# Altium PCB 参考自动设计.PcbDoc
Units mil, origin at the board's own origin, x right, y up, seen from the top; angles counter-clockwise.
Board outline 2362.2 x 2362.2 mil, 2 copper layers (Top Layer, Bottom Layer); 30 components, 18 nets, 92 pads, 180 vias.
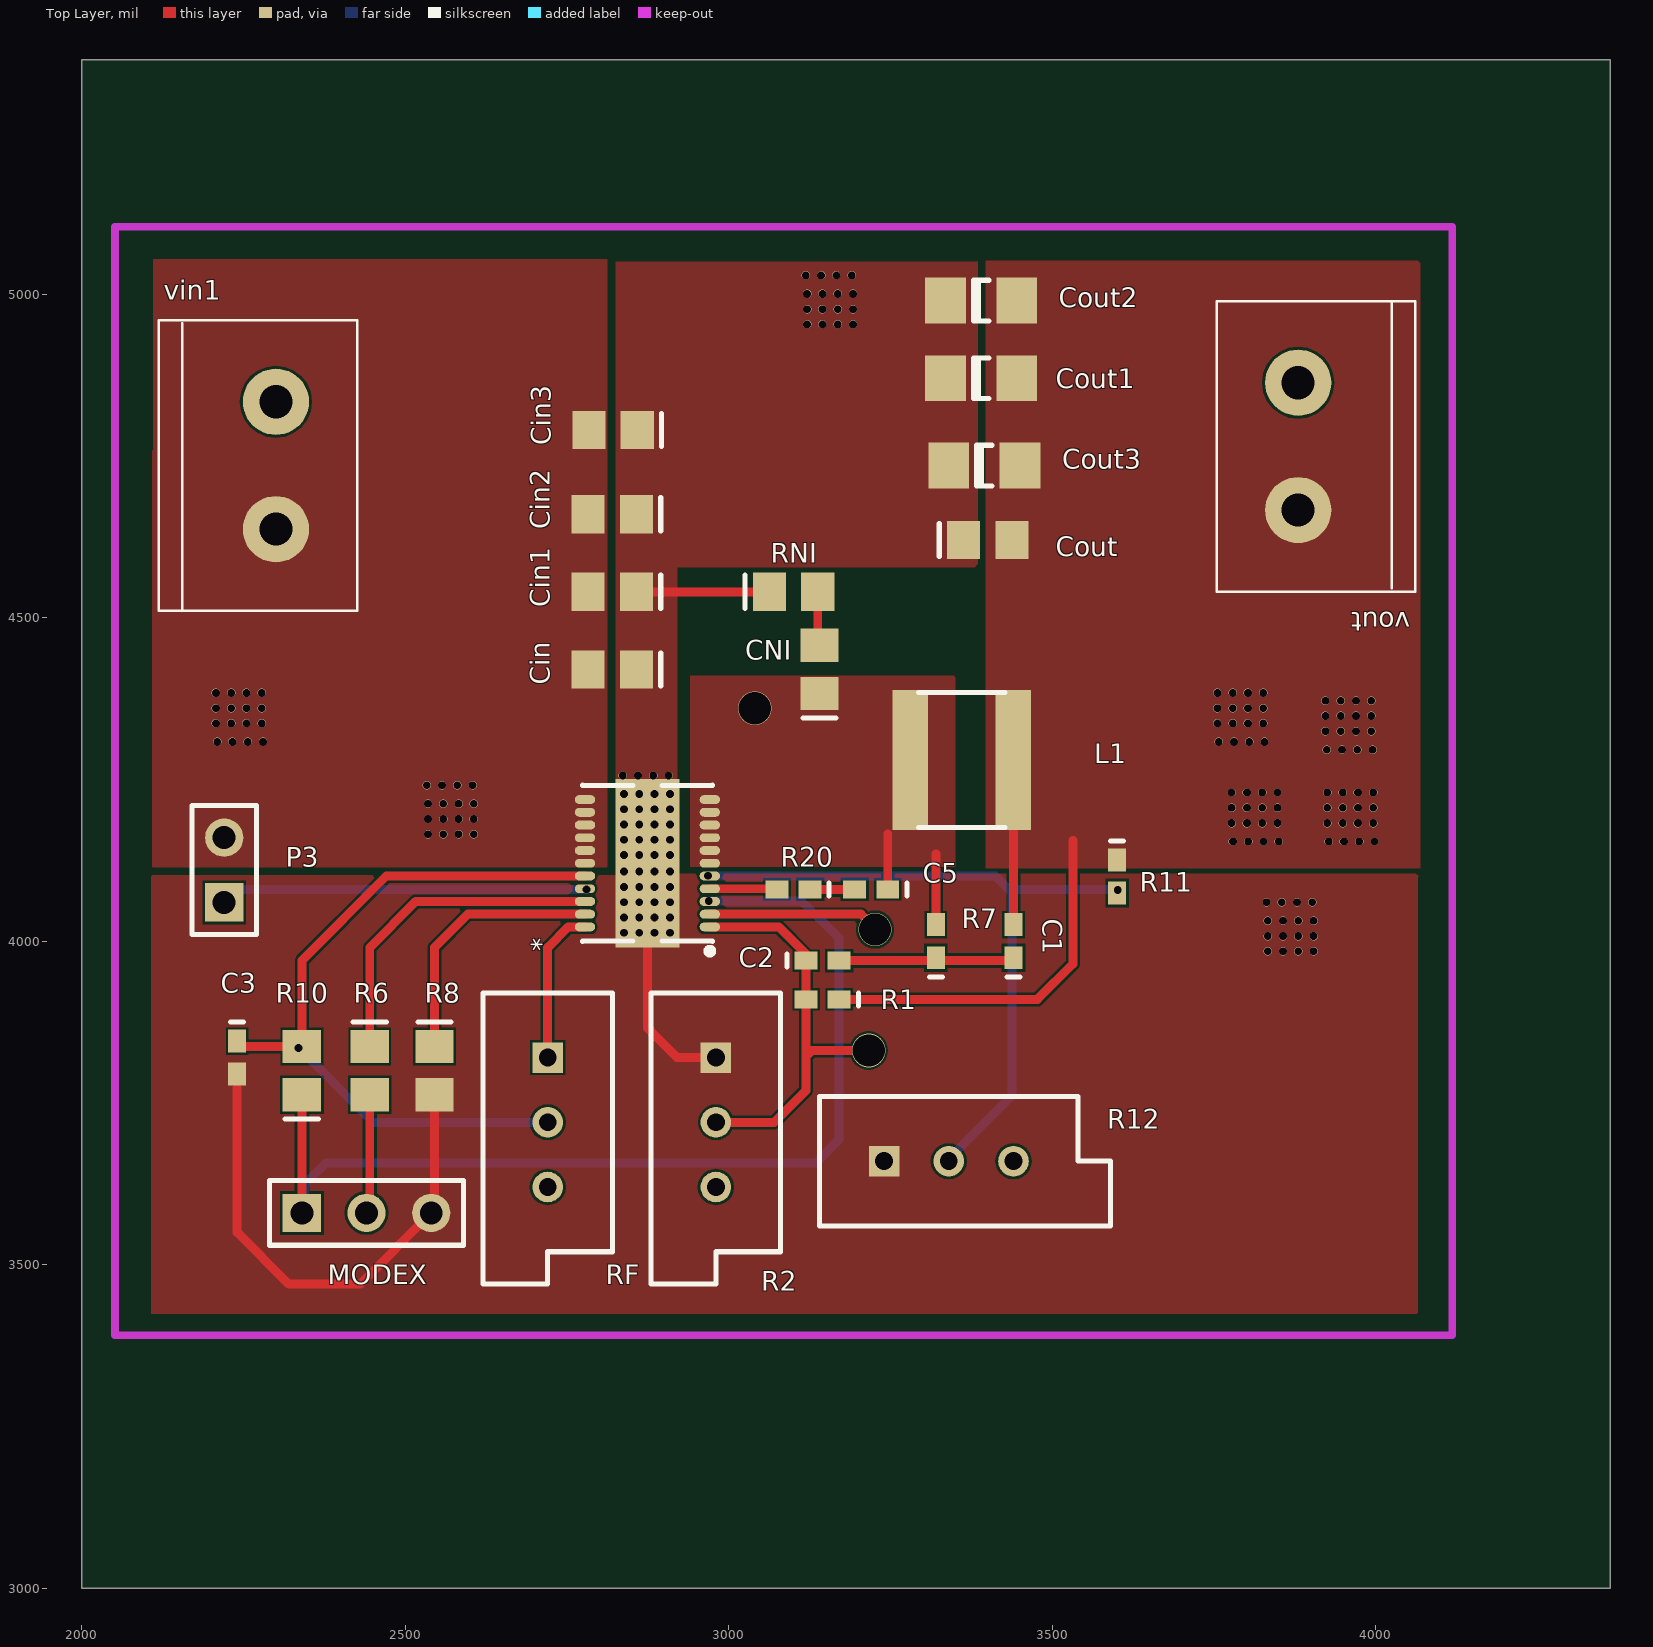
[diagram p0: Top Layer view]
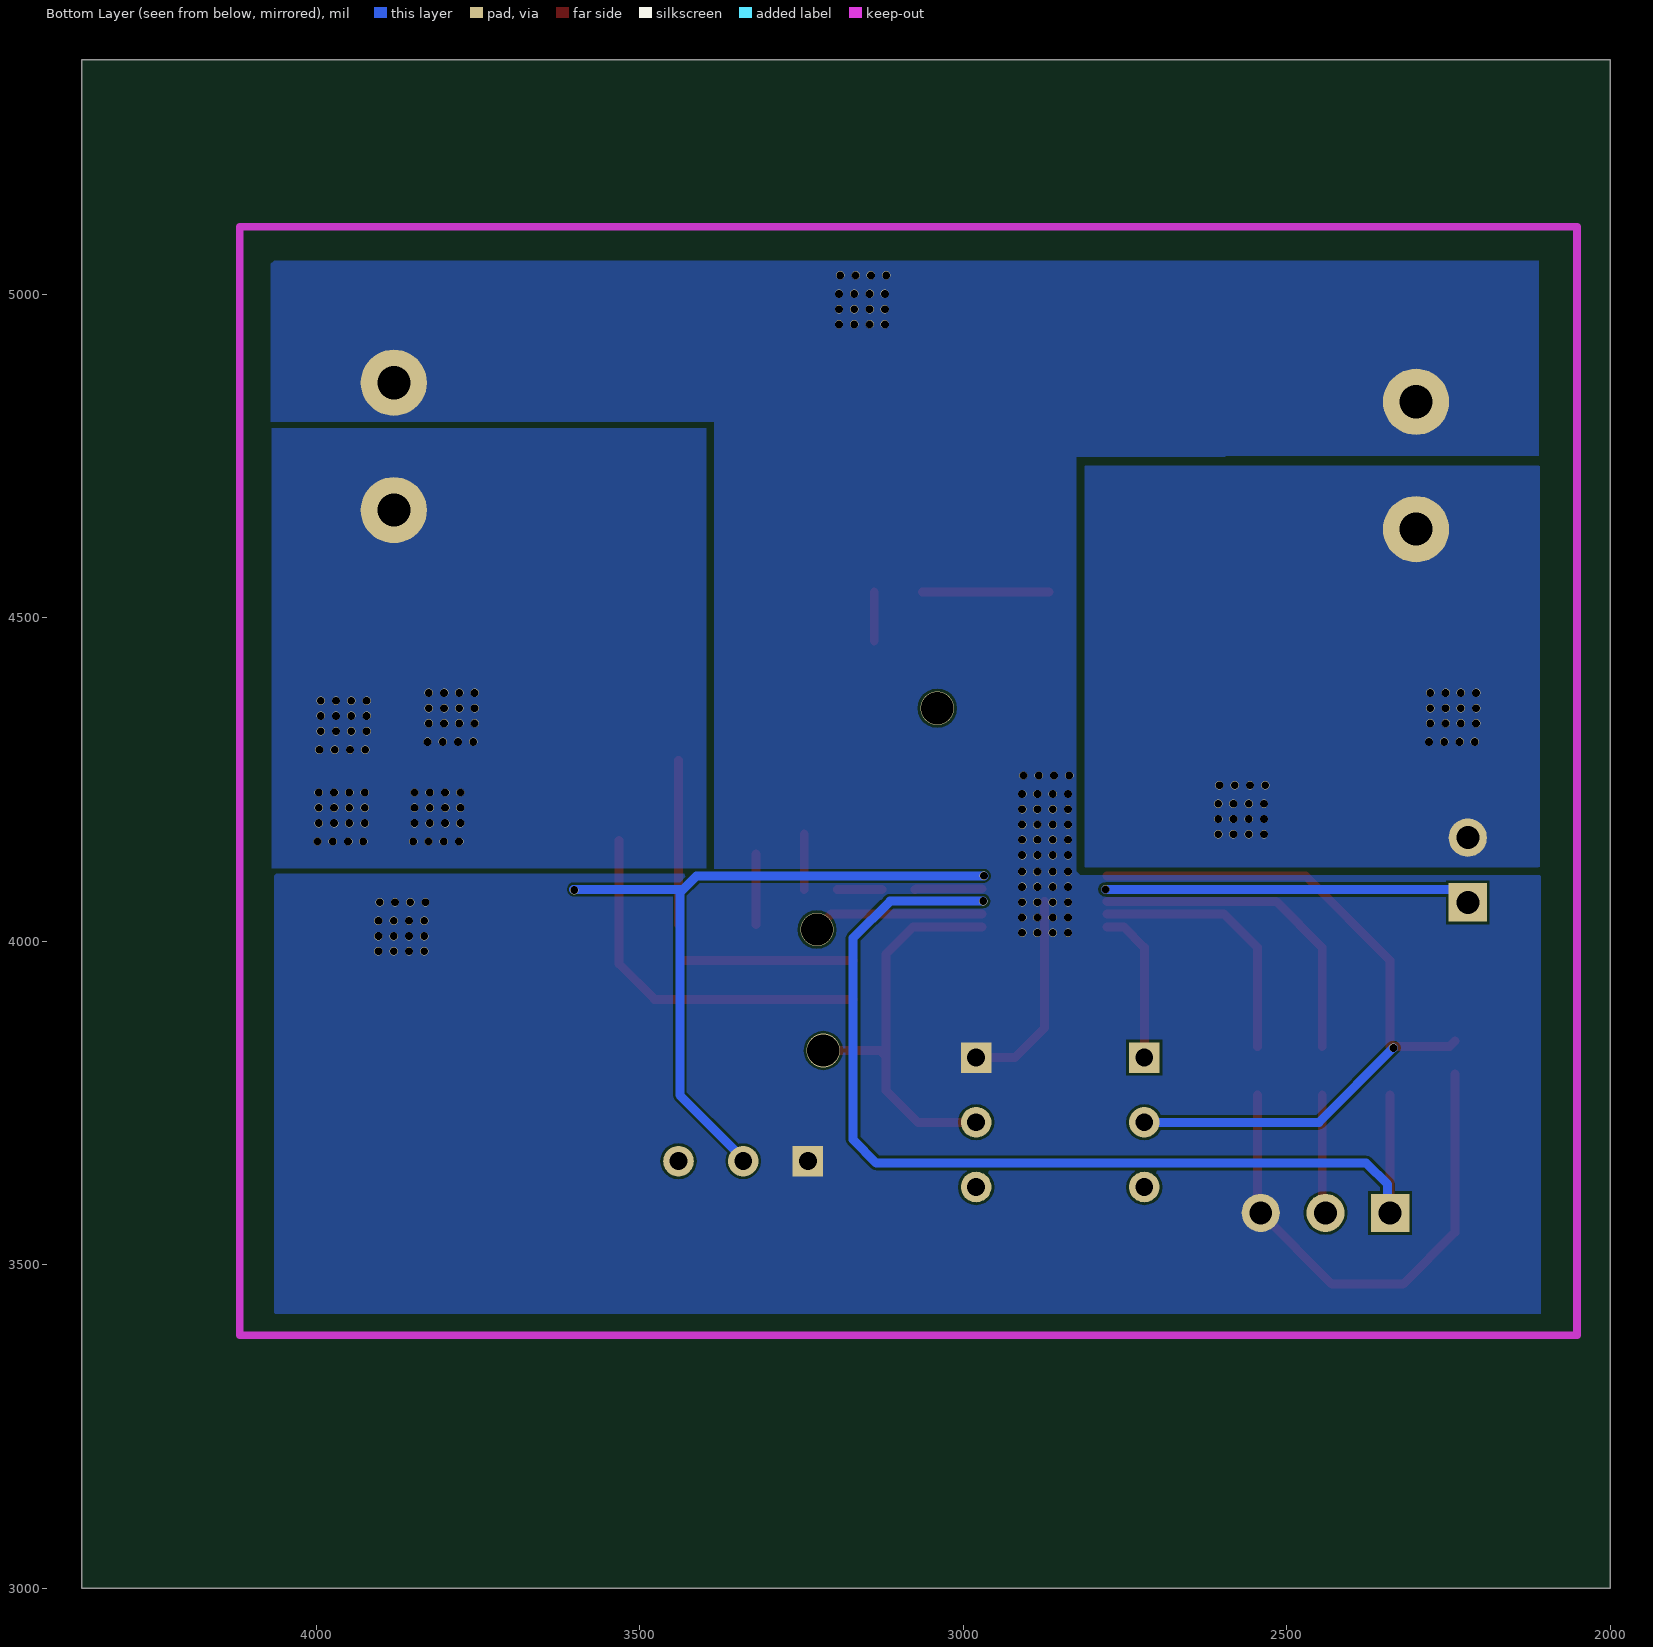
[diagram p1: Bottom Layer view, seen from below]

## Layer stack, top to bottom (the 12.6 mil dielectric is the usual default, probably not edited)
Top Layer: signal copper 1.4
Dielectric: dielectric 12.6, FR-4, Dk 4.8
Bottom Layer: signal copper 1.4

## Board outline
2000,3000 4362.2,3000 4362.2,5362.2 2000,5362.2

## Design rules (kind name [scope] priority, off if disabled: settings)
Clearance [All] p1: gap=4
PlaneConnect [All] p1: planeconnectstyle=Direct reliefexpansion=20 reliefentries=4 reliefconductorwidth=10 reliefairgap=10
PolygonConnect [All] p1: connectstyle=Direct reliefconductorwidth=10 reliefentries=4 polygonreliefangle="90 Angle"
RoutingVias [All] p1: holewidth=23.62 width=39.37 viastyle="Through Hole" minholewidth=28 minwidth=50 maxholewidth=28 maxwidth=50
SilkscreenOverComponentPads [All] p1: minsilkscreentomaskgap=10
SolderMaskExpansion [All] p1: expansion=4
Width [All] p1: maxlimit=20 minlimit=7.87 preferedwidth=7.87
26 further rules are at their usual default settings.

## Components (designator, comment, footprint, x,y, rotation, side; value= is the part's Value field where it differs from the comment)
* "TPS53319" QFN0P601X500X150-22N 3260,4585 r90 top
C1 "Cap" 0402 3440,4000 r90 top
C2 "Cap" 0402 3145,3970 r0 top
C3 "Cap" 0402 2240,3820 r270 top
C5 "Cap" 0402 3220,4080 r180 top
Cin "Cap" 0805 2820,4420 r180 top
Cin1 "Cap" 0805 2820,4540 r180 top
Cin2 "Cap" 0805 2820,4660 r180 top
Cin3 "Cap" 0805 2821,4790 r180 top
CNI "Cap" 0805 3140,4420 r90 top
Cout "Cap" 0805 3400,4620 r0 top
Cout1 "Cap" 1206 3390,4870 r0 top
Cout2 "Cap" 1206 3390,4990 r0 top
Cout3 "Cap" 1206 3395,4735 r0 top
L1 "Inductor" Chip2PinSM127P600-8N 3360,4280 r0 top
MODEX "Header 3" HDR1X3 2340,3580 r0 top
P3 "VDD" HDR1X2 2220,4060 r90 top
R1 "Res2" 0402 3145,3910 r180 top
R2 "Res2" 滑动电阻器 2980,3720 r270 top
R6 "Res2" 0805 2445,3800 r270 top
R7 "Res2" 0402 3320,4000 r90 top
R8 "Res2" 0805 2545,3800 r270 top
R10 "Res2" 0805 2340,3800 r90 top
R11 "Res2" 0402 3600,4100 r270 top
R12 "Res2" 滑动电阻器 3340,3660 r0 top
R20 "Res2" 0402 3100,4080 r180 top
RF "Res2" 滑动电阻器 2720,3720 r270 top
RNI "Res2" 0805 3100,4540 r0 top
vin1 "接线柱" 接线柱 2300,4440 r90 top
vout "接线柱" 接线柱 3880,5060 r270 top

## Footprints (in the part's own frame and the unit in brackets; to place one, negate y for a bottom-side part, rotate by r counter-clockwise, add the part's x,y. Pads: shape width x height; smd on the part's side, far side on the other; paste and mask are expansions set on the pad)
0402 [mm] "Chip Capacitor; Body 1.0 x 0.5 mm (LxW typ)"
  rect 0.9x0.7 smd: 1(-0.65,0) 2(0.65,0)
  silkscreen extent -1.4,-0.25 -1.4,0.25
0805 [mm] "Chip Capacitor; Body 2.0 x 1.2 mm (LxW typ)"
  rect 1.3x1.5 smd: 1(-0.95,0) 2(0.95,0)
  silkscreen extent -1.9,-0.65 -1.9,0.65
1206 [mm] "Chip Capacitor; Body 3.2 x 1.6 mm (LxW typ)"
  rect 1.6x1.8 smd: 1(-1.4,0) 2(1.4,0)
  silkscreen extent -0.3,-0.8 0.3,0.8
Chip2PinSM127P600-8N [mm]
  rect 1.4x5.5 smd: 1(-2.02,0) 2(2.02,0)
  silkscreen extent -1.7,-2.65 1.7,2.65, body extent -3.18,-3.28 3.18,3.28, height 2.1
HDR1X2 [mm] "Connector; Header; 2 Position"
  rect 1.5x1.5 hole 0.9: 1(0,0)
  round 1.5 hole 0.9: 2(2.54,0)
  silkscreen extent -1.27,-1.27 3.81,1.27
HDR1X3 [mm] "Connector; Header; 3 Position"
  rect 1.5x1.5 hole 0.9: 1(0,0)
  round 1.5 hole 0.9: 2(2.54,0) 3(5.08,0)
  silkscreen extent -1.27,-1.27 6.35,1.27
QFN0P601X500X150-22N [mm] "QFN, 22-Leads, Body 5.1x6.1mm (max), Pitch 0.50mm, Pitch1 0.00mm, IPC Medium Density"
  oval 0.35x0.8 smd: 1(-14.3,7.35) 2(-13.8,7.35) 3(-13.3,7.35) 4(-12.8,7.35) 5(-12.3,7.35) 6(-11.8,7.35) 7(-11.3,7.35) 8(-10.8,7.35) 9(-10.3,7.35) 10(-9.8,7.35) 11(-9.3,7.35) 12(-9.3,12.25) 13(-9.8,12.25) 14(-10.3,12.25) 15(-10.8,12.25) 16(-11.3,12.25) 17(-11.8,12.25) 18(-12.3,12.25) 19(-12.8,12.25) 20(-13.3,12.25) 21(-13.8,12.25) 22(-14.3,12.25)
  rect 3.6x2.5 smd: 23(-13.3,9.8) 23(-10.3,9.8)
  rect 3.2x0 smd: 24(-13.4,9.8) 28(-10.2,9.8)
  rect 0x3.2 smd: 25(-11.8,11.4) 26(-11.8,11.4) 29(-11.8,8.2) 30(-11.8,8.2)
  silkscreen extent -15.37,7.22 -8.72,12.35, body extent -14.85,7.25 -8.75,12.35, height 1.5
接线柱 [mm]
  round 2.6 hole 1.3 paste+0.254: 1(5,0) 2(10,0)
  silkscreen extent 1.8,-3.2 13.2,4.6
滑动电阻器 [mm] "Variable Resistor, Thru-Hole; 3 Leads"
  rect 1.2x1.2 hole 0.7: 1(-2.54,0)
  round 1.2 hole 0.7: 2(0,0) 3(2.54,0)
  silkscreen extent -5.08,-2.54 6.35,2.54

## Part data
C1 C2 C3 C5 Cin Cin1 Cin2 Cin3 CNI Cout Cout1 Cout2 Cout3: "Capacitor"
MODEX: "Header, 3-Pin"
P3: library part "Header 2", "Header, 2-Pin"
R1 R2 R6 R7 R8 R10 R11 R12 R20 RF RNI: "Resistor"

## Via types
v1: diameter 13, hole 12, Top Layer to Bottom Layer, 177 vias
v2: diameter 52, hole 50, Top Layer to Bottom Layer, 2 vias
v3: diameter 51, hole 50, Top Layer to Bottom Layer, 1 vias

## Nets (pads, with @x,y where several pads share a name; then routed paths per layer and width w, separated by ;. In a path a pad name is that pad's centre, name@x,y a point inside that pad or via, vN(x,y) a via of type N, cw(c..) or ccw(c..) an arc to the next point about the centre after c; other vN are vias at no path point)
EN: *.2 | length 268.6
  Top Layer w13.78: *.2 3204.31,4041.69 v3@3229,4017
  other v3: 3226,4018
FB: *.1 C2.1 R1.2 R2.2 | length 642.6
  Top Layer w13.78: *.1 3077.01,4022.01 3119.41,3979.61 R1.2 3119.41,3822 ; R2.2 3070,3720 3119.41,3769.41 3119.41,3822 ; v2@3222,3830.78 3128.19,3830.78 3119.41,3822
  other v2: 3216,3831
GND: *.23 C3.2 Cin1.1 Cin2.1 Cin3.1 Cin.1 Cout1.1 Cout2.1 Cout3.1 Cout.1 MODEX.3 R2.1 R8.2 R12.1 RNI.1 vin1.2 vout.1 | length 1323.7
  Top Layer w13.78: C3.2 2240,3550 2320,3470 2430,3470 MODEX.3 2545,3585 R8.2 ; Cin1.1@2867,4540 RNI.1 ; *.23@2874.17,4061.38 2874.17,3865.83 2920,3820 R2.1
  other v1: 2838,4013 2861.62,4013 2885.24,4013 2908.87,4013 2838,4036.62 2861.62,4036.62 2885.24,4036.62 2908.87,4036.62 2838,4060.24 2861.62,4060.24 2885.24,4060.24 2908.87,4060.24 2838,4083.87 2861.62,4083.87 2885.24,4083.87 2908.87,4083.87 2838,4107.49 2861.62,4107.49 2885.24,4107.49 2908.87,4107.49 2838,4133 2861.62,4133 2885.24,4133 2908.87,4133 2838,4156.62 2861.62,4156.62 2885.24,4156.62 2908.87,4156.62 2838,4180.24 2861.62,4180.24 2885.24,4180.24 2908.87,4180.24 2838,4203.87 2861.62,4203.87 2885.24,4203.87 2908.87,4203.87 2838,4227.49 2861.62,4227.49 2885.24,4227.49 2908.87,4227.49 2836,4256 2859.62,4256 2883.24,4256 2906.87,4256
MODE: *.20 R6.1 | length 514.9
  Top Layer w13.78: R6.1 2445,3990 2516.38,4061.38 *.20
Net*_5: *.5 R11.2 R12.2 | length 1102.8
  Bottom Layer w13.78: v1(2968,4101) 3412,4101 3438,4075 3438,3762 R12.2@3339,3663 ; 3433,4080 v1@3602,4080
  other v1: 3601,4079
NetC1_1: C1.1 C2.2 R7.1 | length 266.4
  Top Layer w13.78: C2.2 C1.1@3437,3970
NetC5_2: C5.2 R20.1 | length 68.8
  Top Layer w13.78: R20.1 C5.2
NetCNI_2: CNI.2 RNI.2 | length 76.4
  Top Layer w13.78: CNI.2@3137.4,4463.6 RNI.2
NetMODEX_2: MODEX.2 R6.2 | length 184.7
  Top Layer w13.78: MODEX.2 2445,3585 R6.2
PGOOD: *.3 MODEX.1 R10.1 | length 1621
  Top Layer w13.78: MODEX.1 R10.1
  Bottom Layer w13.78: MODEX.1@2341,3578 2344,3581 2344,3624 2377,3657 3134,3657 3170,3693 3170,4005 3113,4062 v1(2969,4062)
RF: *.22 RF.1 | length 241
  Top Layer w13.78: RF.1 2720,3990 2752.01,4022.01 *.22
SW: *.6 *.7 *.8 *.9 *.10 *.11 C5.1 CNI.1 L1.1 R7.2 | length 195
  Top Layer w13.78: C5.1 3245.59,4165.59 ; R7.2 3320,4135
  other v2: 3040,4360
TIRP: *.21 R8.1 | length 406.7
  Top Layer w13.78: R8.1 2545,3990 2596.69,4041.69 *.21
VBST: *.4 R20.2 | length 104.2
  Top Layer w13.78: *.4 3073.35,4081.06 R20.2
VDD: *.19 P3.1 | length 568.6
  Bottom Layer w13.78: P3.1@2218,4064 2234,4080 v1(2780,4080)
VIN: *.12 *.13 *.14 *.15 *.16 *.17 Cin1.2 Cin2.2 Cin3.2 Cin.2 P3.2 vin1.1
VOUT: C1.2 Cout1.2 Cout2.2 Cout3.2 Cout.2 L1.2 R1.1 R11.1 vout.2 | length 829.1
  Top Layer w13.78: R1.1 3477,3910 3532,3965 3532,4156 ; C1.2 L1.2@3440,4279.53
VREG: *.18 C3.1 R10.2 RF.2 | length 1160.5
  Top Layer w13.78: C3.1 2248.19,3837.4 R10.2 2340,3970 2470.75,4100.75 *.18
  Bottom Layer w13.78: v1(2335,3835) 2450,3720 RF.2
pads on no net: *.24 *.25 *.26 *.28 *.29 *.30 R2.3 R12.3 RF.3
copper on no net:
  other v1: 3833,3984.24 3856.62,3984.24 3880.24,3984.24 3903.87,3984.24 3833,4007.87 3856.62,4007.87 3880.24,4007.87 3903.87,4007.87 3833,4031.49 3856.62,4031.49 3880.24,4031.49 3903.87,4031.49 3831,4060 3854.62,4060 3878.24,4060 3901.87,4060 3779.13,4154 3802.76,4154 3826.38,4154 3850,4154 3927.13,4154 3950.76,4154 3974.38,4154 3998,4154 2535,4165.24 2558.62,4165.24 2582.24,4165.24 2605.87,4165.24 3777.13,4182.51 3800.76,4182.51 3824.38,4182.51 3848,4182.51 3925.13,4182.51 3948.76,4182.51 3972.38,4182.51 3996,4182.51 2535,4188.87 2558.62,4188.87 2582.24,4188.87 2605.87,4188.87 3777.13,4206.13 3800.76,4206.13 3824.38,4206.13 3848,4206.13 3925.13,4206.13 3948.76,4206.13 3972.38,4206.13 3996,4206.13 2535,4212.49 2558.62,4212.49 2582.24,4212.49 2605.87,4212.49 3777.13,4229.76 3800.76,4229.76 3824.38,4229.76 3848,4229.76 3925.13,4229.76 3948.76,4229.76 3972.38,4229.76 3996,4229.76 2533,4241 2556.62,4241 2580.24,4241 2603.87,4241 3924.13,4296 3947.76,4296 3971.38,4296 3995,4296 2209.13,4308 2232.76,4308 2256.38,4308 2280,4308 3757.13,4308 3780.76,4308 3804.38,4308 3828,4308 3922.13,4324.51 3945.76,4324.51 3969.38,4324.51 3993,4324.51 2207.13,4336.51 2230.76,4336.51 2254.38,4336.51 2278,4336.51 3755.13,4336.51 3778.76,4336.51 3802.38,4336.51 3826,4336.51 3922.13,4348.13 3945.76,4348.13 3969.38,4348.13 3993,4348.13 2207.13,4360.13 2230.76,4360.13 2254.38,4360.13 2278,4360.13 3755.13,4360.13 3778.76,4360.13 3802.38,4360.13 3826,4360.13 3922.13,4371.76 3945.76,4371.76 3969.38,4371.76 3993,4371.76 2207.13,4383.76 2230.76,4383.76 2254.38,4383.76 2278,4383.76 3755.13,4383.76 3778.76,4383.76 3802.38,4383.76 3826,4383.76 3121,4953.24 3144.62,4953.24 3168.24,4953.24 3191.87,4953.24 3121,4976.87 3144.62,4976.87 3168.24,4976.87 3191.87,4976.87 3121,5000.49 3144.62,5000.49 3168.24,5000.49 3191.87,5000.49 3119,5029 3142.62,5029 3166.24,5029 3189.87,5029

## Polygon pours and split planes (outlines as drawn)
GND on Top Layer "Bottom Layer-No Net" (solid): 2828,4102 2226,4102 2109,4102 2107,4100 2107,3424 4065,3424 4066,3425 4065,3426 4065,3520 4065,4099 4066,4100 4062,4104 2917,4104 2826,4104 2824,4102
VIN on Top Layer "Bottom Layer-No Net" (solid): 2812,5054 2812,4362 2812,4290 2812,4115 2811,4114 2341,4114 2340,4113 2339,4114 2140,4114 2108,4114 2109,4115 2109,4271 2109,4758 2111,4760 2110,4761 2110,4899 2110,5054 2812,5054
VOUT on Top Layer "Bottom Layer-No Net" (solid): 3397,5052 3397,4689 3397,4113 4069,4113 4069,5048 4071,5050 4069,5052 3394,5052
GND on Top Layer "Bottom Layer-No Net" (solid): 2825,4243.07 2825,4933.27 2825,5050 3385,5050 3385,4583.1 3380,4578.02 2920,4578.02 2920,4243.07 2925,4238 2920,4243.07 2825,4243.07
SW on Top Layer "Bottom Layer-No Net" (solid): 2940,4115 3075,4115 3350,4115 3350,4355 3350,4405 3355,4410 2940,4410 2940,4115
GND on Bottom Layer "Bottom Layer-No Net" (solid): 2894,4622 2903,4631 3367,4631 3367,4622 3385,4604 3385,4514 3385,4064 3379,4058 3373,4064 2892,4064 2892,4613
GND on Bottom Layer "Bottom Layer-No Net" (solid): 4070,4803 4070,5047 4065,5052 4043,5052 2110,5052 2110,4753 2110,4749 2111,4750 2279,4750 2594,4750 2595,4749 2813,4749 3347,4749 3384,4786 3385,4787 3385,4826 3385,4817 3381,4813 3379,4811 3379,4803
GND on Bottom Layer "Bottom Layer-No Net" (solid): 2107,3437 2107,3424 2125,3424 2418,3424 2415,3427 2402,3440 2107,3440
GND on Bottom Layer "Bottom Layer-No Net" (solid): 2410,3424 2107,3424 2107,3441 2107,4100 2109,4102 2118,4102 2819,4102 2820,4103 2825,4108 2825,4110 2825,5050 2832,5050 3385,5050 3385,5045 3385,4583 3380,4578 3376,4578 2920,4578 2920,4570 2920,4104 2939,4104 4062,4104 4065,4101 4065,4097 4065,3426 4063,3424 4031,3424 2116,3424 2107,3424 2107,3436
VIN on Bottom Layer "Bottom Layer-No Net" (solid): 2109,4125.89 2109,4115.32 2111,4114 2152,4114 2492,4114 2648,4114 2811,4114 2812,4114.66 2812,4117.96 2812,4734.34 2811,4735 2801,4735 2110,4735 2109,4734.34 2109,4115.32
VOUT on Bottom Layer "Bottom Layer-No Net" (solid): 4069,4113 4069,4785.76 4069,4793 4051,4793 3711,4793 3400,4793 3397,4793 3397,4792.28 3397,4777.07 3397,4572.13 3398,4571.4 3397,4570.68 3397,4132.55 3397,4113 3405,4113 3814,4113 4069,4113

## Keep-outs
Keep-Out Layer:
  lines w11.81: 2051.18,3391 2051.18,5104 4118,5104 4118,3391 2051.18,3391

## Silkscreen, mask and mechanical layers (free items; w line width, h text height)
Drill Drawing:
  text ".LEGEND" at 952.2,3275 h30
  text "Drill Drawing." at 952.2,3175 h30

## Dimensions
2051.18,3391 to 2051.18,5104 on Mechanical 1
2051.18,3391 to 4118,3391 on Mechanical 1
